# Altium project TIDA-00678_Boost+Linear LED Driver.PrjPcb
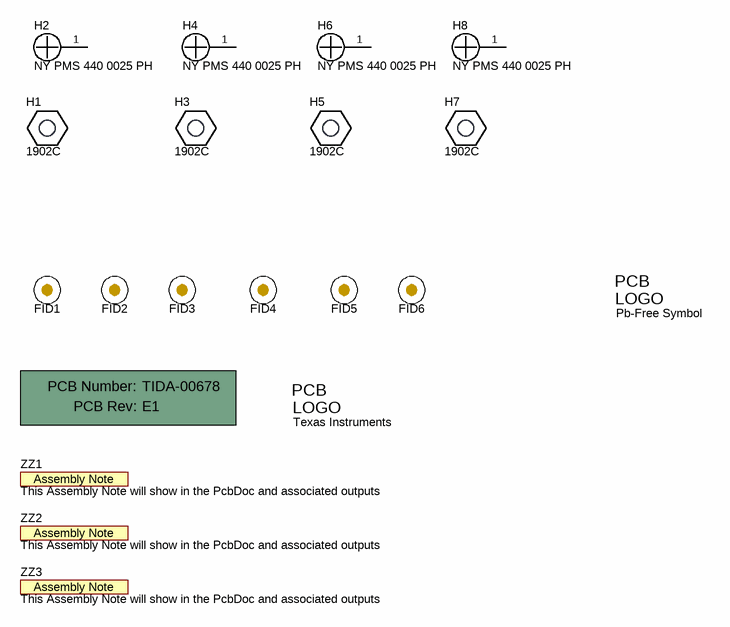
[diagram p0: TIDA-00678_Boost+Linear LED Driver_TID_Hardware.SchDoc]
CopyrightYear: 2015; EVM_Orderable: N/A; PCB_Layout: Robert Regensbureger; PCB_Rev: E1; PRJ_Customer: Public Release; PRJ_Engineer: Robert Regensburger; PRJ_Number: TIDA-00678; PRJ_Title: Boost+Linear LED Driver; SCH_Rev: E1; TechSupport: http://www.ti.com/support; TID: TIDA-00678
3 sheets, 184 parts. Net scope: global (net labels, ports and power ports of the same name join across sheets).
Board file: TIDA-00678_Boost+Linear LED Driver.PcbDoc
Sheets:
  TIDA-00678_Boost+Linear LED Driver_TID_Hardware.SchDoc
  TIDA-00678_Boost+Linear LED Driver 1.SchDoc
  TIDA-00678_Boost+Linear LED Driver 2.SchDoc

## Sheet TIDA-00678_Boost+Linear LED Driver_TID_Hardware.SchDoc: Boost+Linear LED Driver
size 431 x 279 mm; Date: Not shown in title block; ApprovedBy: Not shown in title block; CheckedBy: Not shown in title block; Author: Not shown in title block; CompanyName: Not shown in title block; Engineer: Not shown in title block; Organization: Not shown in title block; Address1: Not shown in title block; Address2: Not shown in title block; Address3: Not shown in title block; Address4: Not shown in title block; DocumentNumber: 4; Revision: Use project parameter SCH_Rev; SheetNumber: 4; SheetTotal: 4; PageSetup: Record=PageOptions¦CenterHorizontal=True¦CenterVertical=True¦PrintScale=1.00¦XCorrection=1.00¦YCorrection=1.00¦PrintKind=0¦BorderSize=5000000¦LeftOffset=0¦BottomOffset=0¦Orientation=2¦PaperLength=1000¦PaperWidth=1000¦Scale=100¦PaperSource=15¦PrintQuality=600¦MediaType=1¦DitherType=10¦PaperKind=Letter¦PrintScaleMode=1

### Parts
!PCB1  Printed Circuit Board  (value not drawn)  (mechanical)
FID1  Fiducial  [Fiducial10-20]  (value not drawn)
FID2  Fiducial  [Fiducial10-20]  (value not drawn)
FID3  Fiducial  [Fiducial10-20]  (value not drawn)
FID4  Fiducial  [Fiducial10-20]  (value not drawn)
FID5  Fiducial  [Fiducial10-20]  (value not drawn)
FID6  Fiducial  [Fiducial10-20]  (value not drawn)
H1  1902C  [Keystone_1902C]
H2  NY PMS 440 0025 PH  [NY PMS 440 0025 PH]
H3  1902C  [Keystone_1902C]
H4  NY PMS 440 0025 PH  [NY PMS 440 0025 PH]
H5  1902C  [Keystone_1902C]
H6  NY PMS 440 0025 PH  [NY PMS 440 0025 PH]
H7  1902C  [Keystone_1902C]
H8  NY PMS 440 0025 PH  [NY PMS 440 0025 PH]
Logo1  Texas Instruments  [TI_Symbol_Overlay_Medium]  (no BOM)
Logo2  Pb-Free Symbol  [Pb-Free_Overlay_Small]  (no BOM)
ZZ1  This Assembly Note will show in the PcbDoc and associated outputs  [AssemblyNote]  (no BOM)
ZZ2  This Assembly Note will show in the PcbDoc and associated outputs  [AssemblyNote]  (no BOM)
ZZ3  This Assembly Note will show in the PcbDoc and associated outputs  [AssemblyNote]  (no BOM)

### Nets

Not connected (* = marked no-connect by the designer): H2 1; H4 1; H6 1; H8 1

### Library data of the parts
!PCB1 = PCB: Manufacturer: Any; PartNumber: TIDA-00678; SymbolCreator: a0412235
FID1-FID6 = Fiducial: Fiducial mark.  There is nothing to buy or mount.; SymbolCreator: codlsc
H1 H3 H5 H7 = 1902C: Standoff, Hex, 0.5"L #4-40 Nylon; Manufacturer: Keystone; CompType: Hardware; SymbolCreator: a0412235
H2 H4 H6 H8 = NY PMS 440 0025 PH: Machine Screw, Round, #4-40 x 1/4, Nylon, Philips panhead; Manufacturer: B&F Fastener Supply; CompType: Hardware; SymbolCreator: codlsc; U/M: EA
Logo1 = TI_Logo: Texas Instrument Corporate Signature; SymbolCreator: a0412235
Logo2 = Pb-Free: SymbolCreator: a0412235
ZZ1-ZZ3 = AssemblyNote: SymbolCreator: codlsc

## Sheet TIDA-00678_Boost+Linear LED Driver 1.SchDoc: Boost+Linear LED Driver
size 431 x 279 mm; Date: Not shown in title block; ApprovedBy: Not shown in title block; CheckedBy: Not shown in title block; Author: Not shown in title block; CompanyName: Not shown in title block; DrawnBy: Robert Regensburger; Engineer: Not shown in title block; Organization: Not shown in title block; Address1: Not shown in title block; Address2: Not shown in title block; Address3: Not shown in title block; Address4: Not shown in title block; DocumentNumber: 2; Revision: Use project parameter SCH_Rev; SheetNumber: 2; SheetTotal: 4; PageSetup: Record=PageOptions¦CenterHorizontal=True¦CenterVertical=True¦PrintScale=0.62¦XCorrection=1.00¦YCorrection=1.00¦PrintKind=0¦BorderSize=5000000¦LeftOffset=0¦BottomOffset=0¦Orientation=2¦PaperLength=1000¦PaperWidth=1000¦Scale=100¦PaperSource=15¦PrintQuality=600¦MediaType=1¦DitherType=10¦PrintScaleMode=1¦PaperKind=Letter
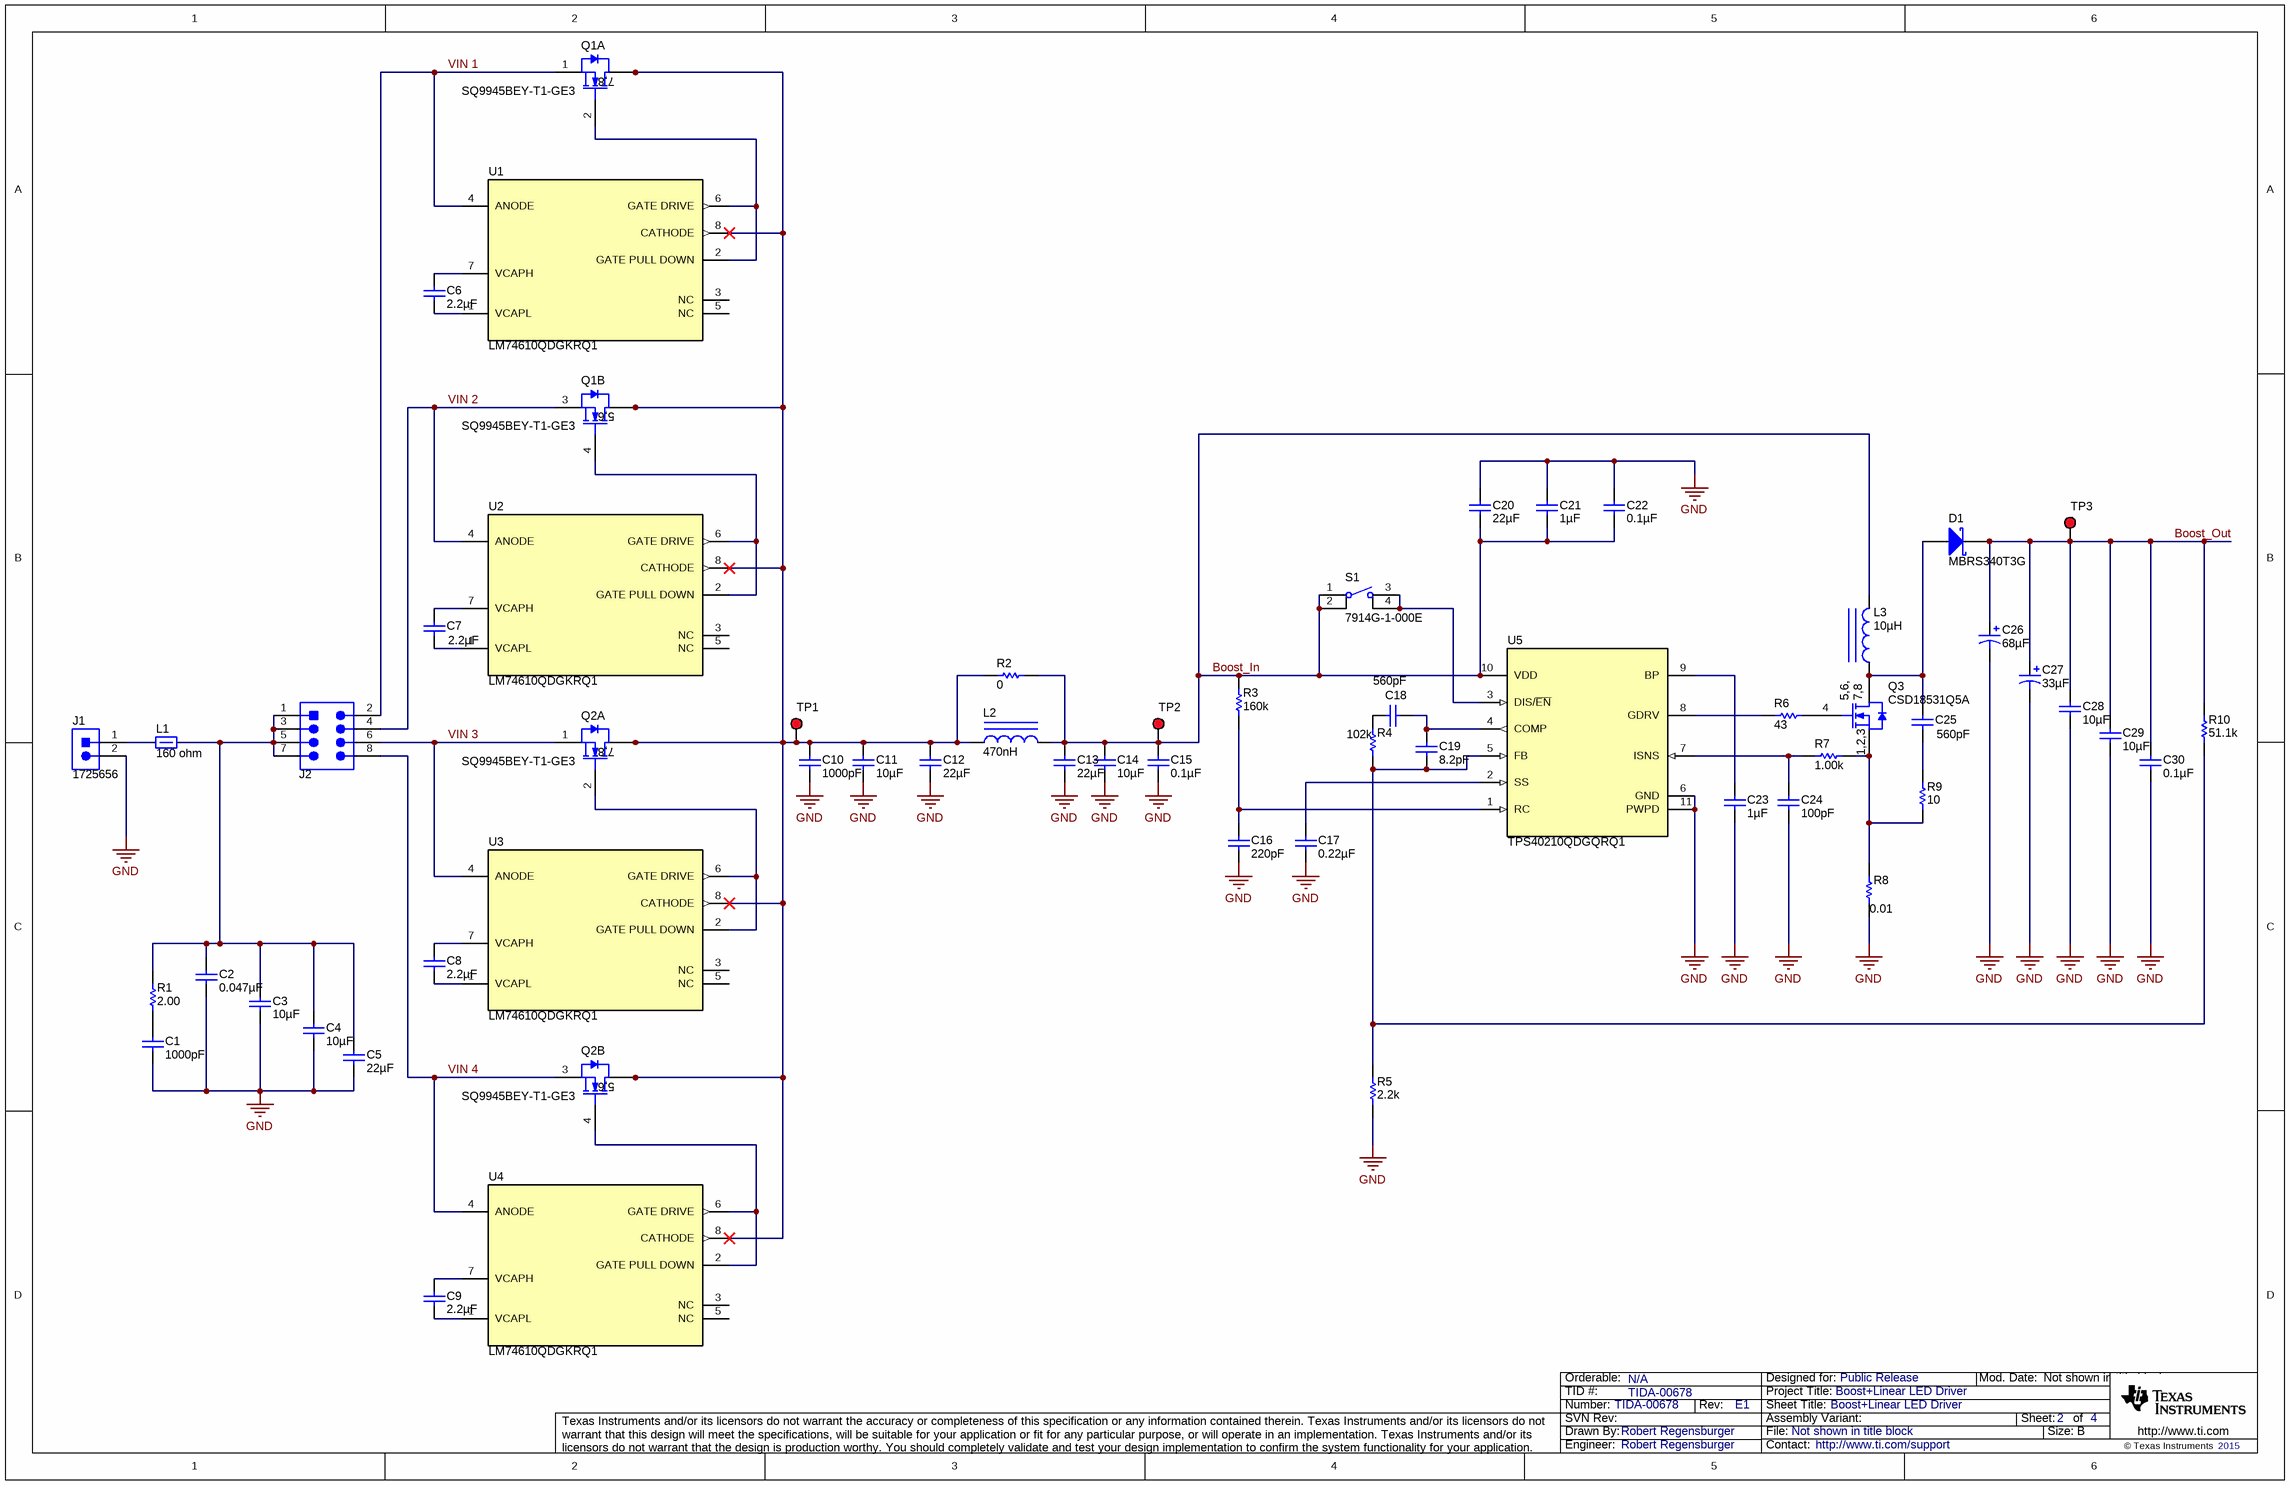
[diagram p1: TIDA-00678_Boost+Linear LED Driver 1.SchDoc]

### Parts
C1  ValueDisplayed: 1000pF  [0603]  (hidden comment: GRM188R72A102KA01D)
C2  ValueDisplayed: 0.047µF  [0603]  (hidden comment: GRM188R71H473KA61D)
C3  ValueDisplayed: 10µF  [1210_270]  (hidden comment: GRM32ER71H106KA12L)
C4  ValueDisplayed: 10µF  [1210_270]  (hidden comment: GRM32ER71H106KA12L)
C5  ValueDisplayed: 22µF  [0805_HV]  (hidden comment: C2012JB1V226M125AC)
C6  ValueDisplayed: 2.2µF  [0805_HV]  (hidden comment: C2012X5R1H225K125AB)
C7  ValueDisplayed: 2.2µF  [0805_HV]  (hidden comment: C2012X5R1H225K125AB)
C8  ValueDisplayed: 2.2µF  [0805_HV]  (hidden comment: C2012X5R1H225K125AB)
C9  ValueDisplayed: 2.2µF  [0805_HV]  (hidden comment: C2012X5R1H225K125AB)
C10  ValueDisplayed: 1000pF  [0603]  (hidden comment: GRM188R72A102KA01D)
C11  ValueDisplayed: 10µF  [1210_270]  (hidden comment: GRM32ER71H106KA12L)
C12  ValueDisplayed: 22µF  [0805_HV]  (hidden comment: C2012JB1V226M125AC)
C13  ValueDisplayed: 22µF  [0805_HV]  (hidden comment: C2012JB1V226M125AC)
C14  ValueDisplayed: 10µF  [1210_270]  (hidden comment: GRM32ER71H106KA12L)
C15  ValueDisplayed: 0.1µF  [0603]  (hidden comment: C1608X7R1H104K080AA)
C16  ValueDisplayed: 220pF  [0603]  (hidden comment: 06035A221FAT2A)
C17  ValueDisplayed: 0.22µF  [0603]  (hidden comment: C0603C224K4RACTU)
C18  ValueDisplayed: 560pF  [0603]  (hidden comment: 06035A561JAT2A)
C19  ValueDisplayed: 8.2pF  [0603]  (hidden comment: 06035A8R2CAT2A)
C20  ValueDisplayed: 22µF  [0805_HV]  (hidden comment: C2012JB1V226M125AC)
C21  ValueDisplayed: 1µF  [0603]  (hidden comment: UMK107AB7105KA-T)
C22  ValueDisplayed: 0.1µF  [0603]  (hidden comment: C1608X7R1H104K080AA)
C23  ValueDisplayed: 1µF  [0603]  (hidden comment: GRM185C81A105KE36D)
C24  ValueDisplayed: 100pF  [0603]  (hidden comment: 06035A101FAT2A)
C25  ValueDisplayed: 560pF  [0603]  (hidden comment: 06035A561JAT2A)
C26  ValueDisplayed: 68µF  [SM_RADIAL_6.3BMM]  (hidden comment: UUD1V680MCL1GS)
C27  ValueDisplayed: 33µF  [SM_RADIAL_6.3BMM]  (hidden comment: EEHZA1H330XP)
C28  ValueDisplayed: 10µF  [1210_270]  (hidden comment: GRM32ER71H106KA12L)
C29  ValueDisplayed: 10µF  [1210_270]  (hidden comment: GRM32ER71H106KA12L)
C30  ValueDisplayed: 0.1µF  [0603]  (hidden comment: C1608X7R1H104K080AA)
D1  MBRS340T3G  [SMC]
J1  1725656  [CONN_1725656]
J2  PEC04DAAN  [CONN_PEC04DAAN]  (value not drawn)
L1  value 160 ohm  [1206M]  (hidden comment: HI1206T161R-10)
L2  ValueDisplayed: 470nH  [WE-LHMI_4020]  (hidden comment: 744373240047)
L3  ValueDisplayed: 10µH  [SRP1250]  (hidden comment: SRP1250-100M)
Q1  SQ9945BEY-T1-GE3  [SOIC-8]  (parts A,B of 2)
Q2  SQ9945BEY-T1-GE3  [SOIC-8]  (parts A,B of 2)
Q3  CSD18531Q5A  [TRANS_NexFET_Q5A]
R1  ValueDisplayed: 2.00  [0603]  (hidden comment: CRCW06032R00FKEA)
R2  ValueDisplayed: 0  [0603]  (hidden comment: CRCW06030000Z0EA)
R3  ValueDisplayed: 160k  [0603]  (hidden comment: CRCW0603160KFKEA)
R4  ValueDisplayed: 102k  [0603]  (hidden comment: CRCW0603102KFKEA)
R5  ValueDisplayed: 2.2k  [0603]  (hidden comment: CRCW06032K20JNEA)
R6  ValueDisplayed: 43  [0603]  (hidden comment: CRCW060343R0JNEA)
R7  ValueDisplayed: 1.00k  [0603]  (hidden comment: CRCW06031K00FKEA)
R8  ValueDisplayed: 0.01  [3015]  (hidden comment: KRL7638-C-R010-F-T1)
R9  ValueDisplayed: 10  [0603]  (hidden comment: CRCW060310R0JNEA)
R10  ValueDisplayed: 51.1k  [0603]  (hidden comment: RC0603FR-0751K1L)
S1  7914G-1-000E  [SW_7914G-1-000E]
TP1  5000  [Keystone5000]  (value not drawn)
TP2  5000  [Keystone5000]  (value not drawn)
TP3  5000  [Keystone5000]  (value not drawn)
U1  LM74610QDGKRQ1  [DGK0008A_N]
U2  LM74610QDGKRQ1  [DGK0008A_N]
U3  LM74610QDGKRQ1  [DGK0008A_N]
U4  LM74610QDGKRQ1  [DGK0008A_N]
U5  TPS40210QDGQRQ1  [DGQ0010D_N]

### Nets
GND: C1.2 C2.2 C3.2 C4.2 C5.2 C10.2 C11.2 C12.2 C13.2 C14.2 C15.2 C16.2 C17.2 C20.1 C21.1 C22.1 C23.2 C24.2 C26.2(-) C27.2(-) C28.2 C29.2 C30.2 J1.2 R5.1 R8.1 U5.6(GND) U5.11(PWPD)  [project net REVGND]
Boost_In: C13.1 C14.1 C15.1 C20.2 C21.2 C22.2 L2.2 L3.2 R2.1 R3.2 S1.1 S1.2 TP2.1 U5.10(VDD)
Boost_Out: C26.1(+) C27.1(+) C28.1 C29.1 C30.1 D1.1(K) R10.2 TP3.1
VIN 1: J2.2 Q1.1(S) U1.4(ANODE)
VIN 2: J2.4 Q1.3(S) U2.4(ANODE)
VIN 3: J2.6 Q2.1(S) U3.4(ANODE)
VIN 4: J2.8 Q2.3(S) U4.4(ANODE)
NetC1_1: C1.1 R1.1
NetC2_1: C2.1 C3.1 C4.1 C5.1 J2.1 J2.3 J2.5 J2.7 L1.2 R1.2
NetC6_1: C6.1 U1.7(VCAPH)
NetC6_2: C6.2 U1.1(VCAPL)
NetC7_1: C7.1 U2.7(VCAPH)
NetC7_2: C7.2 U2.1(VCAPL)
NetC8_1: C8.1 U3.7(VCAPH)
NetC8_2: C8.2 U3.1(VCAPL)
NetC9_1: C9.1 U4.7(VCAPH)
NetC9_2: C9.2 U4.1(VCAPL)
NetC10_1: C10.1 C11.1 C12.1 L2.1 Q1.5(D) Q1.6(D) Q1.7(D) Q1.8(D) Q2.5(D) Q2.6(D) Q2.7(D) Q2.8(D) R2.2 TP1.1 U1.8(CATHODE) U2.8(CATHODE) U3.8(CATHODE) U4.8(CATHODE)
NetC16_1: C16.1 R3.1 U5.1(RC)
NetC17_1: C17.1 U5.2(SS)
NetC18_1: C18.1 C19.1 U5.4(COMP)
NetC18_2: C18.2 R4.2
NetC19_2: C19.2 R4.1 R5.2 R10.1 U5.5(FB)
NetC23_1: C23.1 U5.9(BP)
NetC24_1: C24.1 R7.1 U5.7(ISNS)
NetC25_1: C25.1 D1.2(A) L3.1 Q3.5(D) Q3.6(D) Q3.7(D) Q3.8(D) Q3.9(D)
NetC25_2: C25.2 R9.2
NetJ1_1: J1.1 L1.1
NetQ1_2: Q1.2(G) U1.2(GATE_PULL_DOWN) U1.6(GATE_DRIVE)
NetQ1_4: Q1.4(G) U2.2(GATE_PULL_DOWN) U2.6(GATE_DRIVE)
NetQ2_2: Q2.2(G) U3.2(GATE_PULL_DOWN) U3.6(GATE_DRIVE)
NetQ2_4: Q2.4(G) U4.2(GATE_PULL_DOWN) U4.6(GATE_DRIVE)
NetQ3_1: Q3.1(S) Q3.2(S) Q3.3(S) R7.2 R8.2 R9.1
NetQ3_4: Q3.4(G) R6.2
NetR6_1: R6.1 U5.8(GDRV)
NetS1_3: S1.3 S1.4 U5.3(DIS/~{EN})

Not connected (* = marked no-connect by the designer): U1 3(NC) 5(NC); U2 3(NC) 5(NC); U3 3(NC) 5(NC); U4 3(NC) 5(NC)

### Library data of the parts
C1 C10 = GRM188R72A102KA01D: CAP, CERM, 1000 pF, 100 V, +/- 10%, X7R, 0603; Manufacturer: MuRata; Polarized: N; CompType: Capacitor; Value: 1000pF; U/M: EA; Cap_F: 0.000000001; Tolerance_%: 10; Value1: Unknown; VDC_V: 100; Value2: 100V; TaMin_C: -55; TaMax_C: 125; AEC Category: Q200
C2 = GRM188R71H473KA61D: CAP, CERM, 0.047 µF, 50 V, +/- 10%, X7R, 0603; Manufacturer: MuRata; Polarized: N; CompType: Capacitor; Value: 0.047uF; U/M: EA; Cap_F: 0.000000047; Tolerance_%: 10; Value1: Unknown; VDC_V: 50; Value2: 50V; TaMin_C: -55; TaMax_C: 125; AEC Category: Q200
C3 C4 C11 C14 C28 C29 = GRM32ER71H106KA12L: CAP, CERM, 10 µF, 50 V, +/- 10%, X7R, 1210; Manufacturer: MuRata; Polarized: N; CompType: Capacitor; Value: 10uF; U/M: EA; Cap_F: 0.00001; Tolerance_%: 10; Value1: Unknown; VDC_V: 50; Value2: 50V; TaMin_C: -55; TaMax_C: 125; Cap_Case: 1210; AEC Category: Q200
C5 C12 C13 C20 = C2012JB1V226M125AC: CAP, CERM, 22 µF, 35 V, +/- 20%, JB, 0805; Manufacturer: TDK; Polarized: N; CompType: Capacitor; Value: 22uF; U/M: EA; Cap_F: 0.000022; Tolerance_%: 20; Value1: Unknown; VDC_V: 35; Value2: 35V; TaMin_C: -25; TaMax_C: 85; Cap_Case: 0805; AEC Category: Q200
C6-C9 = C2012X5R1H225K125AB: CAP, CERM, 2.2 µF, 50 V, +/- 10%, X5R, 0805; Manufacturer: TDK; Polarized: N; CompType: Capacitor; Value: 2.2uF; U/M: EA; Cap_F: 0.0000022; Tolerance_%: 10; Value1: Unknown; VDC_V: 50; Value2: 50V; TaMin_C: -55; TaMax_C: 85; Cap_Case: 0805; AEC Category: Q200
C15 C22 C30 = C1608X7R1H104K080AA: CAP, CERM, 0.1 µF, 50 V, +/- 10%, X7R, 0603; Manufacturer: TDK; Polarized: N; CompType: Capacitor; Value: 0.1uF; U/M: EA; Cap_F: 0.0000001; Tolerance_%: 10; Value1: Unknown; VDC_V: 50; Value2: 50V; TaMin_C: -55; TaMax_C: 125; AEC Category: Q200
C16 = 06035A221FAT2A: CAP, CERM, 220 pF, 50 V, +/- 1%, C0G/NP0, 0603; Manufacturer: AVX; Polarized: N; CompType: Capacitor; Value: 220pF; U/M: EA; Cap_F: 0.00000000022; Tolerance_%: 1; ESR_ohm: 0.083; Value1: 0.083 ohm; VDC_V: 50; Value2: 50V; TaMin_C: -55; TaMax_C: 125; AEC Category: Q200
C17 = C0603C224K4RACTU: CAP, CERM, 0.22 µF, 16 V, +/- 10%, X7R, 0603; Manufacturer: Kemet; Polarized: N; CompType: Capacitor; Value: 0.22uF; U/M: EA; Cap_F: 0.00000022; Tolerance_%: 10; Value1: Unknown; VDC_V: 16; Value2: 16V; TaMin_C: -55; TaMax_C: 125; AEC Category: Q200
C18 C25 = 06035A561JAT2A: CAP, CERM, 560 pF, 50 V, +/- 5%, C0G/NP0, 0603; Manufacturer: AVX; Polarized: N; CompType: Capacitor; Value: 560pF; U/M: EA; Cap_F: 0.00000000056; Tolerance_%: 5; ESR_ohm: 0.059; Value1: 0.059 ohm; VDC_V: 50; Value2: 50V; TaMin_C: -55; TaMax_C: 125; AEC Category: Q200
C19 = 06035A8R2CAT2A: CAP, CERM, 8.2 pF, 50 V, +/- 3%, C0G/NP0, 0603; Manufacturer: AVX; Polarized: N; CompType: Capacitor; Value: 8.2pF; U/M: EA; Cap_F: 0.0000000000082; Tolerance_%: 3; ESR_ohm: 0.452; Value1: 0.452 ohm; VDC_V: 50; Value2: 50V; TaMin_C: -55; TaMax_C: 125; AEC Category: Q200
C21 = UMK107AB7105KA-T: CAP, CERM, 1 µF, 50 V, +/- 10%, X7R, 0603; Manufacturer: Taiyo Yuden; Polarized: N; CompType: Capacitor; Value: 1uF; U/M: EA; Cap_F: 0.000001; Tolerance_%: 10; Value1: Unknown; VDC_V: 50; Value2: 50V; TaMin_C: -55; TaMax_C: 125; AEC Category: Q200
C23 = GRM185C81A105KE36D: CAP, CERM, 1 µF, 10 V, +/- 10%, X6S, 0603; Manufacturer: MuRata; Polarized: N; CompType: Capacitor; Value: 1uF; U/M: EA; Cap_F: 0.000001; Tolerance_%: 10; Value1: Unknown; Value2: 10V; TaMin_C: -55; TaMax_C: 105; AEC Category: Q200
C24 = 06035A101FAT2A: CAP, CERM, 100 pF, 50 V, +/- 1%, C0G/NP0, 0603; Manufacturer: AVX; Polarized: N; CompType: Capacitor; Value: 100pF; U/M: EA; Cap_F: 0.0000000001; Tolerance_%: 1; Value1: Unknown; VDC_V: 50; Value2: 50V; TaMin_C: -55; TaMax_C: 125; AEC Category: Q200
C26 = UUD1V680MCL1GS: CAP, AL, 68 µF, 35 V, +/- 20%, 0.34 ohm, SMD; Manufacturer: Nichicon; Polarized: Y; CompType: Capacitor; Value: 68uF; U/M: EA; Cap_F: 0.000068; Tolerance_%: 20; VDC_V: 35; Value2: 35V; ESR_ohm: 0.34; IRMS_A: 0.28; TaMin_C: -55; TaMax_C: 105; Cap_Case: 6.3x7.7; AEC Category: Q200
C27 = EEHZA1H330XP: CAP, Polymer Hybrid, 33 µF, 50 V, +/- 20%, 40 ohm, 6.3x7.7 SMD; Manufacturer: Panasonic; Polarized: Y; CompType: Capacitor; Value: 33uF; U/M: EA; Cap_F: 0.000033; Tolerance_%: 20; Value1: 40 ohm; VDC_V: 50; Value2: 50V; ESR_ohm: 40; IRMS_A: 1.6; TaMin_C: -55; TaMax_C: 105; AEC Category: Q200
D1 = MBRS340T3G: Diode, Schottky, 40 V, 3 A, SMC; Manufacturer: ON Semiconductor; U/M: EA; Vf_V: 0.525; Value: 40V; Value1: 3A; Value2: 0.525V; Io_A: 3; Vr_V: 40; TJmax_C: 125; RJC_CperW: 11; AEC Category: Q101
J1 = 1725656: Terminal Block, 100mil, 2x1, 6A, 63V, TH; Manufacturer: Phoenix Contact; SymbolCreator: a0412235
J2 = PEC04DAAN: Header, 100mil, 4x2, Tin, TH; Manufacturer: Sullins Connector Solutions; SymbolCreator: a0411947; Pitch_mm: 2.54; Gender: Male; Shrouded: N; Row_Count: 2; Current_A: 3; Voltage_V: 1800; Cert_UL: Y
L1 = HI1206T161R-10: Ferrite Bead, 160 ohm @ 100 MHz, 6 A, 1206; Manufacturer: Laird-Signal Integrity Products; Imax_A: 6; DCR_ohm: 0.018; Value1: 0.018 ohm; Value2: 6A; ZTyp@100MHz_Ohm: 160; Ztyp@1GHz_Ohm: 127
L2 = 744373240047: Inductor, Shielded Drum Core, Powdered Iron, 470 nH, 6.8 A, 0.0112 ohm, SMD; Manufacturer: Wurth Elektronik; Value: 470nH; Ind_H: 470.0E-9; Imax_A: 6.8; Irms: 6.8A @ 40C rise; Isat: 14.5A @ 20% inductance drop; DCR_ohm: 0.0112; Value2: 6.8A; AEC Category: Q200
L3 = SRP1250-100M: Inductor, Powdered Iron, 10 µH, 10 A, 0.0255 ohm, SMD; Manufacturer: Bourns; Value: 10uH; Ind_H: 10.0E-6; Imax_A: 10; Irms: 10A @ 40C rise; Isat: 16A @ 20% inductance drop; DCR_ohm: 0.0255; Value2: 10A; AEC Category: Q200
Q1 Q2 = SQ9945BEY-T1-GE3: MOSFET, N-CH, 60 V, 5.4 A, SOIC-8; Manufacturer: Vishay-Siliconix; Alternate Manufacturer: None; U/M: EA; ChType: N; Value: 60V; VdsMax_V: 60; Value1: 0.082 ohm; Rdson45_ohm: 0.082; Value2: 8 nC; QgTyp_nC: 8; Vgs_V: 20; IdsMax_A: 5.4; AEC Category: Q101
Q3 = CSD18531Q5A: MOSFET, N-CH, 60 V, 19 A, SON 5x6mm; Manufacturer: Texas Instruments; Alternate Manufacturer: None; U/M: EA; ChType: N; Value: 60V; VdsMax_V: 60; Value1: 0.0044 ohm; Rdson45_ohm: 0.0044; Value2: 18 nC; QgTyp_nC: 18; Vgs_V: 20; IdsMax_A: 19; AEC Category: Q101
R1 = CRCW06032R00FKEA: RES, 2.00, 1%, 0.1 W, 0603; Manufacturer: Vishay-Dale; CompType: Resistor; Value: 2.00; Res_ohm: 2; Value_Code: 2R00; Tolerance_%: 1; Power_W: 0.1; Value2: 0.1W; VDC_V: 75; TempCo: 100 ppm/C; EIA_Code: E96; U/M: EA; AEC Category: Q200
R2 = CRCW06030000Z0EA: RES, 0, 5%, 0.1 W, 0603; Manufacturer: Vishay-Dale; CompType: Resistor; Value: 0; Value_Code: 0000; Tolerance_%: 5; Power_W: 0.1; Value2: 0.1W; VDC_V: 75; TempCo: 200 ppm/C; EIA_Code: E24; U/M: EA; AEC Category: Q200
R3 = CRCW0603160KFKEA: RES, 160 k, 1%, 0.1 W, 0603; Manufacturer: Vishay-Dale; CompType: Resistor; Value: 160k; Res_ohm: 160000; Tolerance_%: 1; Power_W: 0.1; Value2: 0.1W; VDC_V: 75; TempCo: 100 ppm/C; U/M: EA; AEC Category: Q200
R4 = CRCW0603102KFKEA: RES, 102 k, 1%, 0.1 W, 0603; Manufacturer: Vishay-Dale; CompType: Resistor; Value: 102k; Res_ohm: 102000; Tolerance_%: 1; Power_W: 0.1; Value2: 0.1W; VDC_V: 75; TempCo: 100 ppm/C; EIA_Code: E96; U/M: EA; AEC Category: Q200
R5 = CRCW06032K20JNEA: RES, 2.2 k, 5%, 0.1 W, 0603; Manufacturer: Vishay-Dale; CompType: Resistor; Value: 2.2k; Res_ohm: 2200; Value_Code: 2k20; Tolerance_%: 5; Power_W: 0.1; Value2: 0.1W; VDC_V: 75; TempCo: 200 ppm/C; EIA_Code: E24; U/M: EA; AEC Category: Q200
R6 = CRCW060343R0JNEA: RES, 43, 5%, 0.1 W, 0603; Manufacturer: Vishay-Dale; CompType: Resistor; Value: 43; Value_Code: 43R0; Tolerance_%: 5; Power_W: 0.1; Value2: 0.1W; VDC_V: 75; TempCo: 200 ppm/C; EIA_Code: E24; U/M: EA; AEC Category: Q200
R7 = CRCW06031K00FKEA: RES, 1.00 k, 1%, 0.1 W, 0603; Manufacturer: Vishay-Dale; CompType: Resistor; Value: 1.00k; Res_ohm: 1000; Value_Code: 1k00; Tolerance_%: 1; Power_W: 0.1; Value2: 0.1W; VDC_V: 75; TempCo: 100 ppm/C; EIA_Code: E96; U/M: EA; AEC Category: Q200
R8 = KRL7638-C-R010-F-T1: RES, 0.01, 1%, 4 W, 3015 WIDE; Manufacturer: Susumu Co Ltd; CompType: Resistor; Value: 0.01; Value_Code: R010; Tolerance_%: 1; Power_W: 4; Value2: 4W; TempCo: 50 ppm/C; EIA_Code: E96; U/M: EA; AEC Category: Q200
R9 = CRCW060310R0JNEA: RES, 10, 5%, 0.1 W, 0603; Manufacturer: Vishay-Dale; CompType: Resistor; Value: 10; Value_Code: 10R0; Tolerance_%: 5; Power_W: 0.1; Value2: 0.1W; VDC_V: 75; TempCo: 200 ppm/C; EIA_Code: E24; U/M: EA; AEC Category: Q200
R10 = RC0603FR-0751K1L: RES, 51.1 k, 1%, 0.1 W, 0603; Manufacturer: Yageo America; CompType: Resistor; Value: 51.1k; Res_ohm: 51100; Value_Code: 51k1; Tolerance_%: 1; Power_W: 0.1; Value2: 0.1W; VDC_V: 150; TempCo: 200 ppm/C; EIA_Code: E96; U/M: EA; AEC Category: Q200
S1 = 7914G-1-000E: Switch, Tactile, SPST-NO, 0.1A, 16V, SMT; Manufacturer: Bourns; SymbolCreator: a0412235; VDC_V: 16; SwitchFunction: Off-Mom; PositionCount: 1; CurrentRating_mA: 100
TP1-TP3 = 5000: Test Point, Miniature, Red, TH; Manufacturer: Keystone; CompType: Test Point Loop; ContactFinish: Silver
U1-U4 = LM74610QDGKRQ1: Smart Diode Controller, DGK0008A; Manufacturer: Texas Instruments; SymbolCreator: Altium; CompType: IC; U/M: EA
U5 = TPS40210QDGQRQ1: 4.5-V TO 52-V INPUT CURRENT MODE BOOST CONTROLLER, DGQ0010D; Manufacturer: Texas Instruments; SymbolCreator: a0412235; CompType: IC; U/M: EA

## Sheet TIDA-00678_Boost+Linear LED Driver 2.SchDoc: Boost+Linear LED Driver
size 431 x 279 mm; Date: Not shown in title block; ApprovedBy: Not shown in title block; CheckedBy: Not shown in title block; Author: Not shown in title block; CompanyName: Not shown in title block; DrawnBy: Robert Regensburger; Engineer: Not shown in title block; Organization: Not shown in title block; Address1: Not shown in title block; Address2: Not shown in title block; Address3: Not shown in title block; Address4: Not shown in title block; DocumentNumber: 3; Revision: Use project parameter SCH_Rev; SheetNumber: 3; SheetTotal: 4; PageSetup: Record=PageOptions¦CenterHorizontal=True¦CenterVertical=True¦PrintScale=0.66¦XCorrection=1.00¦YCorrection=1.00¦PrintKind=0¦BorderSize=5000000¦LeftOffset=0¦BottomOffset=0¦Orientation=2¦PaperLength=2970¦PaperWidth=2100¦Scale=100¦PaperSource=7¦PrintQuality=600¦MediaType=1¦DitherType=10¦PrintScaleMode=1¦PaperKind=A4¦PaperIndex=9
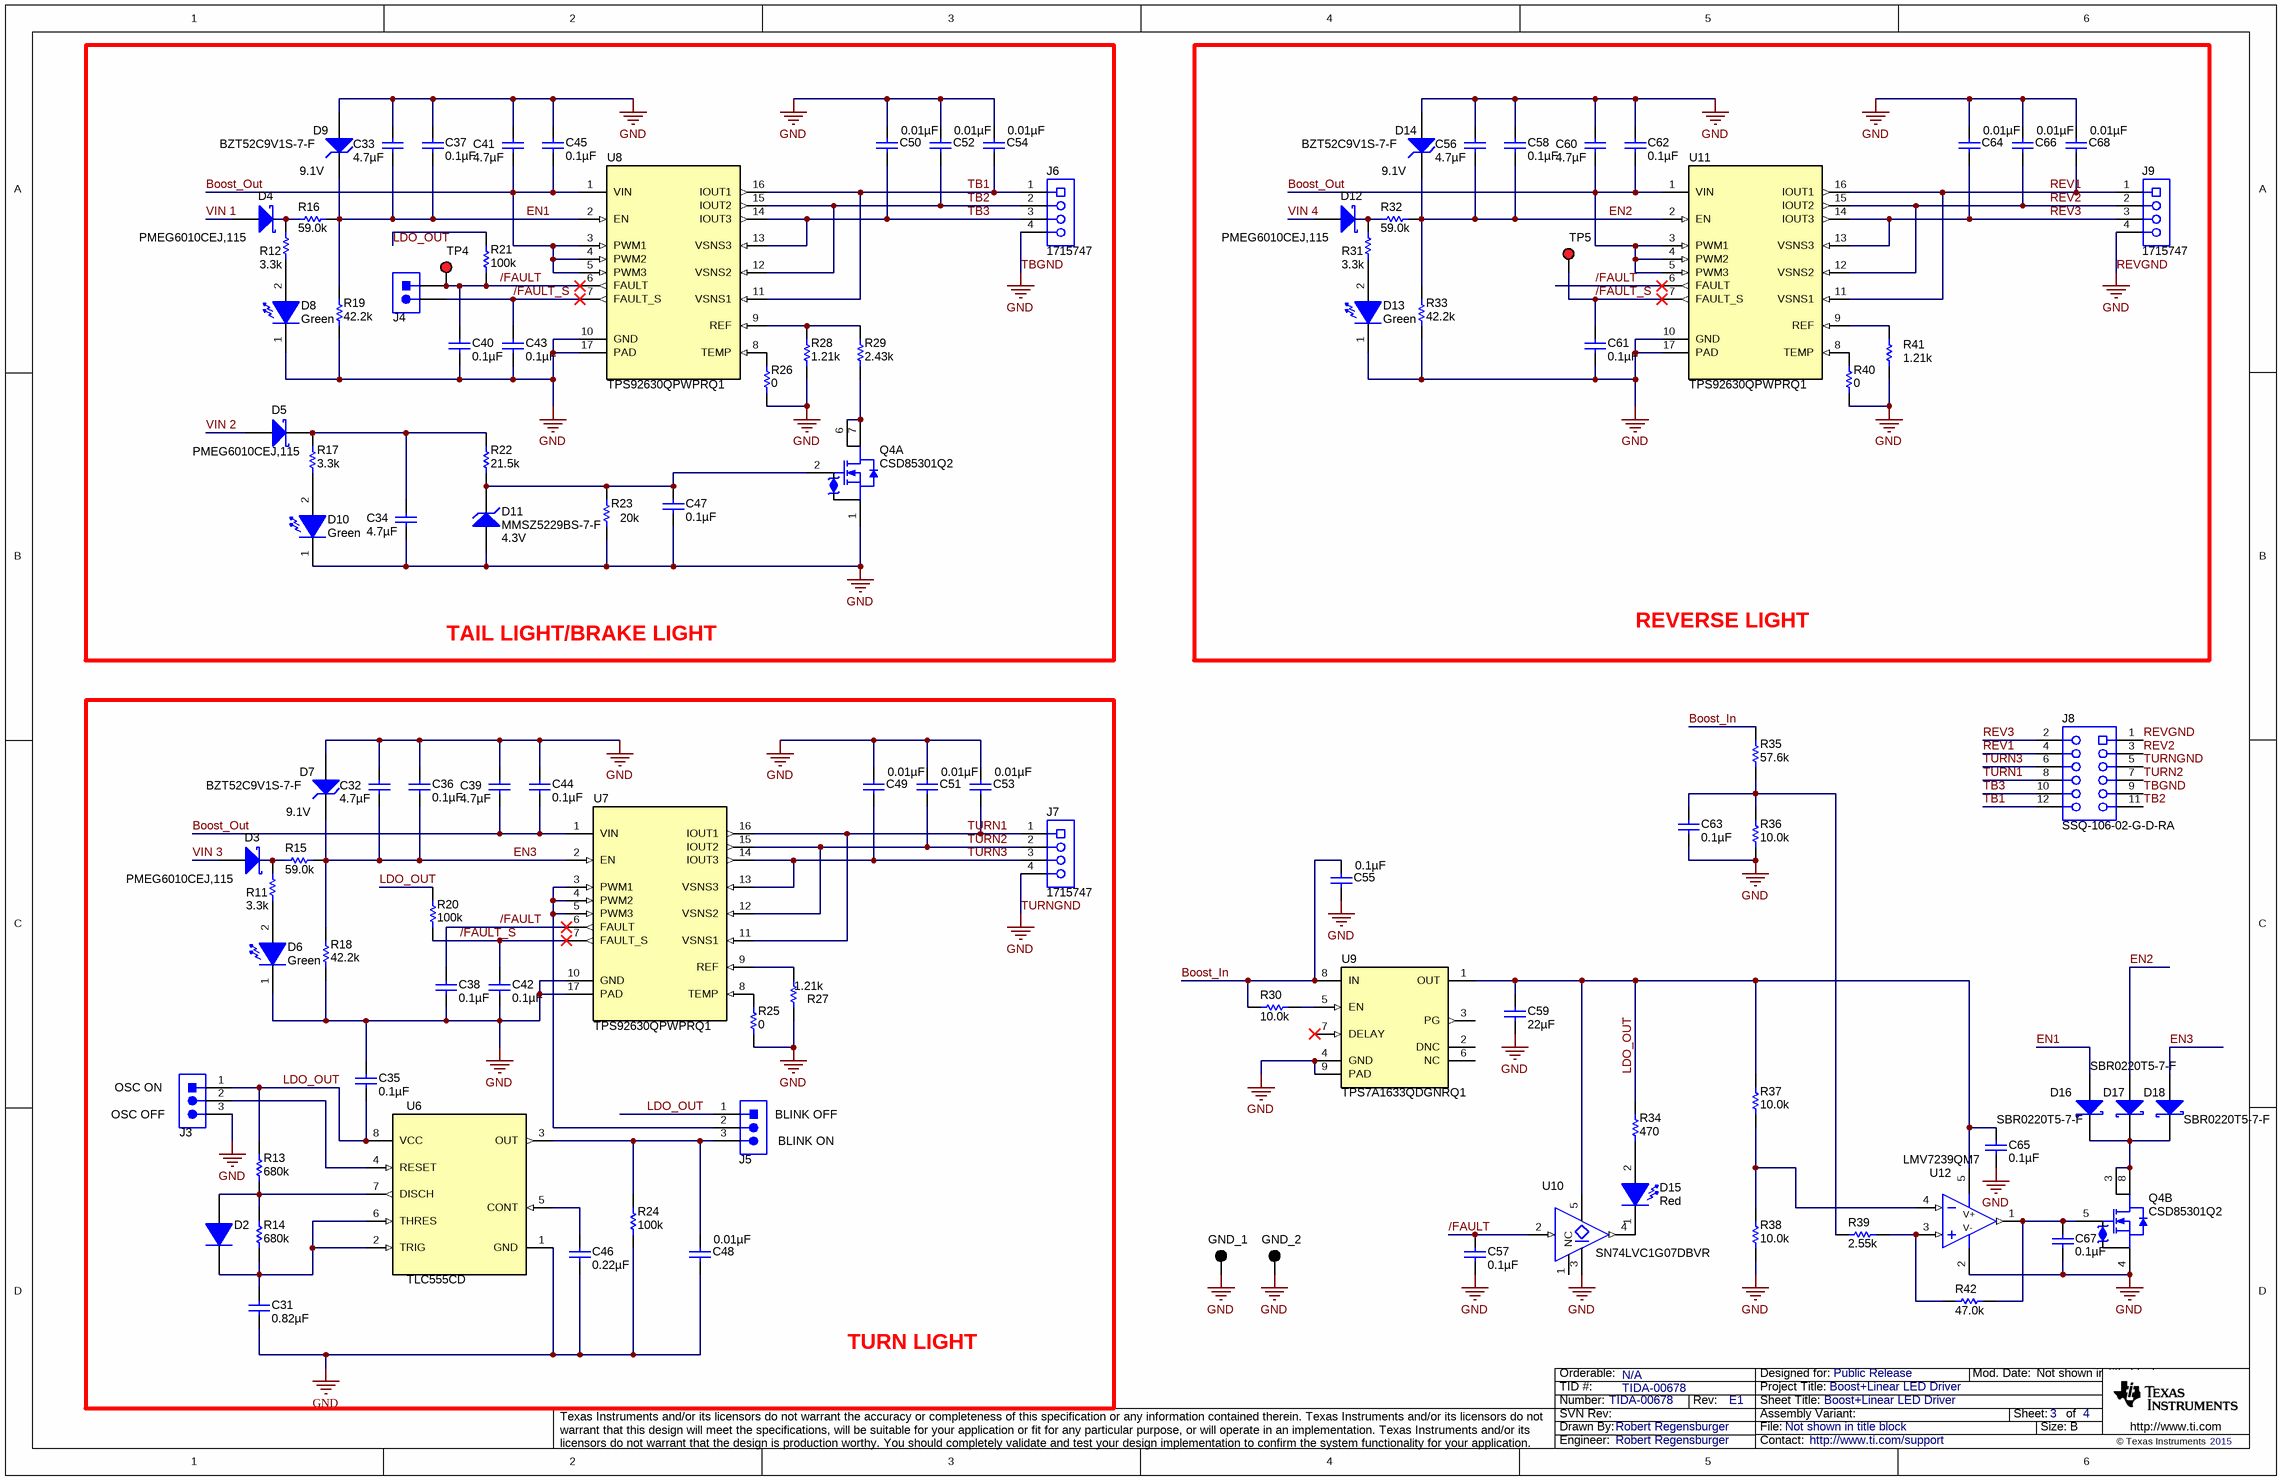
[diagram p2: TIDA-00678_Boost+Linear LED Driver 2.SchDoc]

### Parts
C31  ValueDisplayed: 0.82µF  [0805_HV]  (hidden comment: GRM219R71E824KA88D)
C32  ValueDisplayed: 4.7µF  [1206]  (hidden comment: GRM31CR71H475KA12L)
C33  ValueDisplayed: 4.7µF  [1206]  (hidden comment: GRM31CR71H475KA12L)
C34  ValueDisplayed: 4.7µF  [1206]  (hidden comment: GRM31CR71H475KA12L)
C35  ValueDisplayed: 0.1µF  [0603]  (hidden comment: 06035C104KAT2A)
C36  ValueDisplayed: 0.1µF  [0603]  (hidden comment: 06035C104KAT2A)
C37  ValueDisplayed: 0.1µF  [0603]  (hidden comment: 06035C104KAT2A)
C38  ValueDisplayed: 0.1µF  [0603]  (hidden comment: 06035C104KAT2A)
C39  ValueDisplayed: 4.7µF  [1206]  (hidden comment: GRM31CR71H475KA12L)
C40  ValueDisplayed: 0.1µF  [0603]  (hidden comment: 06035C104KAT2A)
C41  ValueDisplayed: 4.7µF  [1206]  (hidden comment: GRM31CR71H475KA12L)
C42  ValueDisplayed: 0.1µF  [0603]  (hidden comment: 06035C104KAT2A)
C43  ValueDisplayed: 0.1µF  [0603]  (hidden comment: 06035C104KAT2A)
C44  ValueDisplayed: 0.1µF  [0603]  (hidden comment: 06035C104KAT2A)
C45  ValueDisplayed: 0.1µF  [0603]  (hidden comment: 06035C104KAT2A)
C46  ValueDisplayed: 0.22µF  [0805_HV]  (hidden comment: 0805YC224JAT2A)
C47  ValueDisplayed: 0.1µF  [0603]  (hidden comment: 06035C104KAT2A)
C48  ValueDisplayed: 0.01µF  [0603]  (hidden comment: 06031C103JAT2A)
C49  ValueDisplayed: 0.01µF  [0603]  (hidden comment: 06031C103JAT2A)
C50  ValueDisplayed: 0.01µF  [0603]  (hidden comment: 06031C103JAT2A)
C51  ValueDisplayed: 0.01µF  [0603]  (hidden comment: 06031C103JAT2A)
C52  ValueDisplayed: 0.01µF  [0603]  (hidden comment: 06031C103JAT2A)
C53  ValueDisplayed: 0.01µF  [0603]  (hidden comment: 06031C103JAT2A)
C54  ValueDisplayed: 0.01µF  [0603]  (hidden comment: 06031C103JAT2A)
C55  ValueDisplayed: 0.1µF  [0603]  (hidden comment: C1608X7R1H104K)
C56  ValueDisplayed: 4.7µF  [1206]  (hidden comment: GRM31CR71H475KA12L)
C57  ValueDisplayed: 0.1µF  [0603]  (hidden comment: 0603YC104JAT2A)
C58  ValueDisplayed: 0.1µF  [0603]  (hidden comment: 06035C104KAT2A)
C59  ValueDisplayed: 22µF  [0603]  (hidden comment: C1608X5R1A226M080AC)
C60  ValueDisplayed: 4.7µF  [1206]  (hidden comment: GRM31CR71H475KA12L)
C61  ValueDisplayed: 0.1µF  [0603]  (hidden comment: 06035C104KAT2A)
C62  ValueDisplayed: 0.1µF  [0603]  (hidden comment: 06035C104KAT2A)
C63  ValueDisplayed: 0.1µF  [0603]  (hidden comment: 06035C104KAT2A)
C64  ValueDisplayed: 0.01µF  [0603]  (hidden comment: 06031C103JAT2A)
C65  ValueDisplayed: 0.1µF  [0603]  (hidden comment: 0603YC104JAT2A)
C66  ValueDisplayed: 0.01µF  [0603]  (hidden comment: 06031C103JAT2A)
C67  ValueDisplayed: 0.1µF  [0603]  (hidden comment: 0603YC104JAT2A)
C68  ValueDisplayed: 0.01µF  [0603]  (hidden comment: 06031C103JAT2A)
D2  1N4148W-7-F  [SOD-123]  (value not drawn)
D3  PMEG6010CEJ,115  [SOD-323F]
D4  PMEG6010CEJ,115  [SOD-323F]
D5  PMEG6010CEJ,115  [SOD-323F]
D6  value Green  [SML-P1_GREEN]  (hidden comment: SML-P12PTT86)
D7  BZT52C9V1S-7-F  value 9.1V  [sod-323]
D8  value Green  [SML-P1_GREEN]  (hidden comment: SML-P12PTT86)
D9  BZT52C9V1S-7-F  value 9.1V  [sod-323]
D10  value Green  [SML-P1_GREEN]  (hidden comment: SML-P12PTT86)
D11  MMSZ5229BS-7-F  value 4.3V  [sod-323]
D12  PMEG6010CEJ,115  [SOD-323F]
D13  value Green  [SML-P1_GREEN]  (hidden comment: SML-P12PTT86)
D14  BZT52C9V1S-7-F  value 9.1V  [sod-323]
D15  value Red  [SML-P1_RED]  (hidden comment: SML-P12UTT86)
D16  SBR0220T5-7-F  [SOD-523]
D17  SBR0220T5-7-F  [SOD-523]
D18  SBR0220T5-7-F  [SOD-523]
GND_1  5011  [Keystone5011]  (value not drawn)
GND_2  5011  [Keystone5011]  (value not drawn)
J3  PEC03SAAN  [CONN_PEC03SAAN]  (value not drawn)
J4  PEC02SAAN  [CONN_PEC02SAAN]  (value not drawn)
J5  PEC03SAAN  [CONN_PEC03SAAN]  (value not drawn)
J6  1715747  [Phoenix_1715747]
J7  1715747  [Phoenix_1715747]
J8  SSQ-106-02-G-D-RA  [SSQ-106-02-G-D-RA]
J9  1715747  [Phoenix_1715747]
Q4  CSD85301Q2  [DQK0006B]  (parts A,B of 2)
R11  ValueDisplayed: 3.3k  [0603]  (hidden comment: CRCW06033K30JNEA)
R12  ValueDisplayed: 3.3k  [0603]  (hidden comment: CRCW06033K30JNEA)
R13  ValueDisplayed: 680k  [0805_HV]  (hidden comment: CRCW0805680KJNEA)
R14  ValueDisplayed: 680k  [0805_HV]  (hidden comment: CRCW0805680KJNEA)
R15  ValueDisplayed: 59.0k  [0603]  (hidden comment: RC0603FR-0759KL)
R16  ValueDisplayed: 59.0k  [0603]  (hidden comment: RC0603FR-0759KL)
R17  ValueDisplayed: 3.3k  [0603]  (hidden comment: CRCW06033K30JNEA)
R18  ValueDisplayed: 42.2k  [0603]  (hidden comment: RC0603FR-0742K2L)
R19  ValueDisplayed: 42.2k  [0603]  (hidden comment: RC0603FR-0742K2L)
R20  ValueDisplayed: 100k  [0603]  (hidden comment: CRCW0603100KFKEA)
R21  ValueDisplayed: 100k  [0603]  (hidden comment: CRCW0603100KFKEA)
R22  ValueDisplayed: 21.5k  [0805_HV]  (hidden comment: CRCW080521K5FKEA)
R23  ValueDisplayed: 20k  [0805_HV]  (hidden comment: CRCW080520K0JNEA)
R24  ValueDisplayed: 100k  [0805_HV]  (hidden comment: CRCW0805100KFKEA)
R25  ValueDisplayed: 0  [0603]  (hidden comment: CRCW06030000Z0EA)
R26  ValueDisplayed: 0  [0603]  (hidden comment: CRCW06030000Z0EA)
R27  ValueDisplayed: 1.21k  [0603]  (hidden comment: CRCW06031K21FKEA)
R28  ValueDisplayed: 1.21k  [0603]  (hidden comment: CRCW06031K21FKEA)
R29  ValueDisplayed: 2.43k  [0603]  (hidden comment: CRCW06032K43FKEA)
R30  ValueDisplayed: 10.0k  [0603]  (hidden comment: CRCW060310K0FKEA)
R31  ValueDisplayed: 3.3k  [0603]  (hidden comment: CRCW06033K30JNEA)
R32  ValueDisplayed: 59.0k  [0603]  (hidden comment: RC0603FR-0759KL)
R33  ValueDisplayed: 42.2k  [0603]  (hidden comment: RC0603FR-0742K2L)
R34  ValueDisplayed: 470  [0603]  (hidden comment: RC0603FR-07470RL)
R35  ValueDisplayed: 57.6k  [0603]  (hidden comment: RC0603FR-0757K6L)
R36  ValueDisplayed: 10.0k  [0603]  (hidden comment: CRCW060310K0FKEA)
R37  ValueDisplayed: 10.0k  [0603]  (hidden comment: CRCW060310K0FKEA)
R38  ValueDisplayed: 10.0k  [0603]  (hidden comment: CRCW060310K0FKEA)
R39  ValueDisplayed: 2.55k  [0603]  (hidden comment: RC0603FR-072K55L)
R40  ValueDisplayed: 0  [0603]  (hidden comment: CRCW06030000Z0EA)
R41  ValueDisplayed: 1.21k  [0603]  (hidden comment: CRCW06031K21FKEA)
R42  ValueDisplayed: 47.0k  [0603]  (hidden comment: RC0603FR-0747KL)
TP4  5000  [Keystone5000]  (value not drawn)
TP5  5000  [Keystone5000]  (value not drawn)
U6  TLC555CD  [D0008A_N]
U7  TPS92630QPWPRQ1  [PWP0016F_N]
U8  TPS92630QPWPRQ1  [PWP0016F_N]
U9  TPS7A1633QDGNRQ1  [DGN0008C_N]
U10  SN74LVC1G07DBVR  [DBV0005A_N]
U11  TPS92630QPWPRQ1  [PWP0016F_N]
U12  LMV7239QM7  [DCK0005A_N]

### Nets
REVGND: C31.2 C32.1 C33.1 C34.2 C35.1 C36.1 C37.1 C38.2 C39.1 C40.2 C41.1 C42.2 C43.2 C44.1 C45.1 C46.2 C47.2 C48.2 C49.1 C50.1 C51.1 C52.1 C53.1 C54.1 C55.2 C56.1 C57.2 C58.1 C59.2 C60.1 C61.2 C62.1 C63.2 C64.1 C65.1 C66.1 C67.1 C68.1 D6.1(K) D7.2(A) D8.1(K) D9.2(A) D10.1(K) D11.2(A) D13.1(K) D14.2(A) GND_1.1 GND_2.1 J3.3 J6.4 J7.4 J8.1 J8.5 J8.9 J9.4 Q4.1(S1) Q4.4(S2) R18.1 R19.1 R23.1 R24.1 R25.1 R26.1 R27.1 R28.1 R33.1 R36.1 R38.1 R40.1 R41.1 U6.1(GND) U7.10(GND) U7.17(PAD) U8.10(GND) U8.17(PAD) U9.4(GND) U9.9(PAD) U10.3(GND) U11.10(GND) U11.17(PAD) U12.2(V-)  [also labelled GND, TBGND, TURNGND]
/FAULT: C38.1 C40.1 C57.1 J4.1 R21.1 TP4.1 U7.6(FAULT) U8.6(FAULT) U10.2(A) U11.6(FAULT)
/FAULT_S: C42.1 C43.1 C61.1 J4.2 R20.1 TP5.1 U7.7(FAULT_S) U8.7(FAULT_S) U11.7(FAULT_S)
Boost_In: C55.1 R30.2 R35.2 U9.8(IN)
Boost_Out: C39.2 C41.2 C44.2 C45.2 C60.2 C62.2 U7.1(VIN) U8.1(VIN) U8.3(PWM1) U8.4(PWM2) U8.5(PWM3) U11.1(VIN) U11.3(PWM1) U11.4(PWM2) U11.5(PWM3)
EN1: C33.2 C37.2 D9.1(K) D16.2(A) R16.2 R19.2 U8.2(EN)
EN2: C56.2 C58.2 D14.1(K) D17.2(A) R32.2 R33.2 U11.2(EN)
EN3: C32.2 C36.2 D7.1(K) D18.2(A) R15.2 R18.2 U7.2(EN)
LDO_OUT: C35.2 C59.1 C65.2 J3.1 J5.1 R13.2 R20.2 R21.2 R34.2 R37.2 U6.8(VCC) U9.1(OUT) U10.5(VCC) U12.5(V+)
REV1: C68.2 J8.4 J9.1 U11.11(VSNS1) U11.16(IOUT1)
REV2: C66.2 J8.3 J9.2 U11.12(VSNS2) U11.15(IOUT2)
REV3: C64.2 J8.2 J9.3 U11.13(VSNS3) U11.14(IOUT3)
TB1: C54.2 J6.1 J8.12 U8.11(VSNS1) U8.16(IOUT1)
TB2: C52.2 J6.2 J8.11 U8.12(VSNS2) U8.15(IOUT2)
TB3: C50.2 J6.3 J8.10 U8.13(VSNS3) U8.14(IOUT3)
TURN1: C53.2 J7.1 J8.8 U7.11(VSNS1) U7.16(IOUT1)
TURN2: C51.2 J7.2 J8.7 U7.12(VSNS2) U7.15(IOUT2)
TURN3: C49.2 J7.3 J8.6 U7.13(VSNS3) U7.14(IOUT3)
VIN 1: D4.2(A)
VIN 2: D5.2(A)
VIN 3: D3.2(A)
VIN 4: D12.2(A)
NetC31_1: C31.1 D2.1(K) R14.1 U6.2(TRIG) U6.6(THRES)
NetC34_1: C34.1 D5.1(K) R17.2 R22.2
NetC46_1: C46.1 U6.5(CONT)
NetC47_1: C47.1 D11.1(K) Q4.2(G1) R22.1 R23.2
NetC48_1: C48.1 J5.3 R24.2 U6.3(OUT)
NetC63_1: C63.1 R35.1 R36.2 R39.1
NetC67_2: C67.2 Q4.5(G2) R42.1 U12.1(OUT)
NetD2_2: D2.2(A) R13.1 R14.2 U6.7(DISCH)
NetD3_1: D3.1(K) R11.2 R15.1
NetD4_1: D4.1(K) R12.2 R16.1
NetD6_2: D6.2(A) R11.1
NetD8_2: D8.2(A) R12.1
NetD10_2: D10.2(A) R17.1
NetD12_1: D12.1(K) R31.2 R32.1
NetD13_2: D13.2(A) R31.1
NetD15_1: D15.1(K) U10.4(Y)
NetD15_2: D15.2(A) R34.1
NetD16_1: D16.1(K) D17.1(K) D18.1(K) Q4.3(D2) Q4.8(D2)
NetJ3_2: J3.2 U6.4(RESET)
NetJ5_2: J5.2 U7.3(PWM1) U7.4(PWM2) U7.5(PWM3)
NetQ4_6: Q4.6(D1) Q4.7(D1) R29.1
NetR25_2: R25.2 U7.8(TEMP)
NetR26_2: R26.2 U8.8(TEMP)
NetR27_2: R27.2 U7.9(REF)
NetR28_2: R28.2 R29.2 U8.9(REF)
NetR30_1: R30.1 U9.5(EN)
NetR37_1: R37.1 R38.2 U12.4(IN-)
NetR39_2: R39.2 R42.2 U12.3(IN+)
NetR40_2: R40.2 U11.8(TEMP)
NetR41_2: R41.2 U11.9(REF)

Not connected (* = marked no-connect by the designer): U9 2(DNC) 3(PG) 6(NC) 7(DELAY)*; U10 1(NC)

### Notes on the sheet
- TAIL LIGHT/BRAKE LIGHT
- REVERSE LIGHT
- (near J3) OSC ON
- (near J3) OSC OFF
- (near J5) BLINK ON
- (near J5) BLINK OFF
- TURN LIGHT

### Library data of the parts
C31 = GRM219R71E824KA88D: CAP, CERM, 0.82 µF, 25 V, +/- 10%, X7R, 0805; Manufacturer: MuRata; Polarized: N; CompType: Capacitor; Value: 0.82uF; U/M: EA; Cap_F: 0.00000082; Tolerance_%: 10; Value1: Unknown; VDC_V: 25; Value2: 25V; TaMin_C: -55; TaMax_C: 125; Cap_Case: 0805; AEC Category: Q200
C32-C34 C39 C41 C56 C60 = GRM31CR71H475KA12L: CAP, CERM, 4.7 µF, 50 V, +/- 10%, X7R, 1206; Manufacturer: MuRata; Polarized: N; CompType: Capacitor; Value: 4.7uF; U/M: EA; Cap_F: 0.0000047; Tolerance_%: 10; Value1: Unknown; VDC_V: 50; Value2: 50V; TaMin_C: -55; TaMax_C: 125; Cap_Case: 2220; AEC Category: Q200
C35-C38 C40 C42-C45 C47 C58 C61-C63 = 06035C104KAT2A: CAP, CERM, 0.1 µF, 50 V, +/- 10%, X7R, 0603; Manufacturer: AVX; Polarized: N; CompType: Capacitor; Value: 0.1uF; U/M: EA; Cap_F: 0.0000001; Tolerance_%: 10; Value1: Unknown; VDC_V: 50; Value2: 50V; TaMin_C: -55; TaMax_C: 125; AEC Category: Q200
C46 = 0805YC224JAT2A: CAP, CERM, 0.22 µF, 16 V, +/- 5%, X7R, 0805; Manufacturer: AVX; Polarized: N; CompType: Capacitor; Value: 0.22uF; U/M: EA; Cap_F: 0.00000022; Tolerance_%: 5; ESR_ohm: 0.016; Value1: 0.016 ohm; VDC_V: 16; Value2: 16V; TaMin_C: -55; TaMax_C: 125; Cap_Case: 0805; AEC Category: Q200
C48-C54 C64 C66 C68 = 06031C103JAT2A: CAP, CERM, 0.01 µF, 100 V, +/- 5%, X7R, 0603; Manufacturer: AVX; Polarized: N; CompType: Capacitor; Value: 0.01uF; U/M: EA; Cap_F: 0.00000001; Tolerance_%: 5; ESR_ohm: 0.098; Value1: 0.098 ohm; VDC_V: 100; Value2: 100V; TaMin_C: -55; TaMax_C: 125; AEC Category: Q200
C55 = C1608X7R1H104K: CAP, CERM, 0.1 µF, 50 V, +/- 10%, X7R, 0603; Manufacturer: TDK; Polarized: N; CompType: Capacitor; Value: 0.1uF; U/M: EA; Cap_F: 0.0000001; Tolerance_%: 10; ESR_ohm: 0.017; Value1: 0.017 ohm; VDC_V: 50; Value2: 50V; TaMin_C: -55; TaMax_C: 125; AEC Category: Q200
C57 C65 C67 = 0603YC104JAT2A: CAP, CERM, 0.1 µF, 16 V, +/- 5%, X7R, 0603; Manufacturer: AVX; Polarized: N; CompType: Capacitor; Value: 0.1uF; U/M: EA; Cap_F: 0.0000001; Tolerance_%: 5; ESR_ohm: 0.039; Value1: 0.039 ohm; VDC_V: 16; Value2: 16V; TaMin_C: -55; TaMax_C: 125; AEC Category: Q200
C59 = C1608X5R1A226M080AC: CAP, CERM, 22 µF, 10 V, +/- 20%, X5R, 0603; Manufacturer: TDK; Polarized: N; CompType: Capacitor; Value: 22uF; U/M: EA; Cap_F: 0.000022; Tolerance_%: 20; Value1: Unknown; VDC_V: 10; Value2: 10V; TaMin_C: -55; TaMax_C: 85; AEC Category: Q200
D2 = 1N4148W-7-F: Diode, Ultrafast, 100 V, 0.15 A, SOD-123; Manufacturer: Diodes Inc.; U/M: EA; Vf_V: 1.25; Value: 100V; Value1: 0.15A; Value2: 1.25V; Io_A: 0.15; Vr_V: 100; TJmax_C: 150; AEC Category: Q101
D3-D5 D12 = PMEG6010CEJ,115: Diode, Schottky, 60 V, 1 A, SOD-323F; Manufacturer: NXP Semiconductor; U/M: EA; Vf_V: 0.66; Value: 60V; Value1: 1A; Value2: 0.66V; Io_A: 1; Vr_V: 60; TJmax_C: 150; AEC Category: Q101
D6 D8 D10 D13 = SML-P12PTT86: LED, Green, SMD; Manufacturer: Rohm; Type: AlInGaP; Vf_V: 2.2; Value2: 2.2V; Io_A: 0.02; Value1: W; U/M: EA
D7 D9 D14 = BZT52C9V1S-7-F: Diode, Zener, 9.1 V, 200 mW, SOD-323; Manufacturer: Diodes Inc.; SymbolCreator: a0412235; U/M: EA; Power_W: 0.2; Vz_V: 9.1; Value1: 0.2W; RJA_CperW: 625; AEC Category: Q101
D11 = MMSZ5229BS-7-F: Diode, Zener, 4.3 V, 200 mW, SOD-323; Manufacturer: Diodes Inc.; SymbolCreator: a0412235; U/M: EA; Power_W: 0.2; Vz_V: 4.3; Value1: 0.2W; RJA_CperW: 350; AEC Category: Q101
D15 = SML-P12UTT86: LED, Red, SMD; Manufacturer: Rohm; Type: AlInGaP; Vf_V: 2; Value2: 2V; Io_A: 0.02; Value1: W; U/M: EA
D16-D18 = SBR0220T5-7-F: Diode, Schottky, 20 V, 0.2 A, SOD-523; Manufacturer: Diodes Inc.; U/M: EA; Vf_V: 0.47; Value: 20V; Value1: 0.2A; Value2: 0.47V; Io_A: 0.2; Vr_V: 20; AEC Category: Q101
GND_1 GND_2 = 5011: Test Point, Multipurpose, Black, TH; Manufacturer: Keystone; CompType: Test Point Loop; ContactFinish: Silver
J3 J5 = PEC03SAAN: Header, 100mil, 3x1, Tin, TH; Manufacturer: Sullins Connector Solutions; SymbolCreator: a0799628; Pitch_mm: 2.54; Gender: Male; Shrouded: N; Row_Count: 1; Current_A: 3; Voltage_V: 1800; Cert_UL: Y
J4 = PEC02SAAN: Header, 100mil, 2x1, Tin plated, TH; Manufacturer: Sullins Connector Solutions; SymbolCreator: a0412235; U/M: EA
J6 J7 J9 = 1715747: Terminal Block, 5.08mm, 4x1, TH; Manufacturer: Phoenix Contact; SymbolCreator: a0411947
J8 = SSQ-106-02-G-D-RA: Receptacle, 100mil, 6x2, Gold, R/A, TH; Manufacturer: Samtec; SymbolCreator: a0412235
Q4 = CSD85301Q2: MOSFET, N-CH, 20 V, 6.7 A, DQK0006B; Manufacturer: Texas Instruments; Alternate Manufacturer: None; SymbolCreator: a0411947; U/M: EA; ChType: N; Value: 20V; VdsMax_V: 20; Value1: 0.023 ohm; Rdson45_ohm: 0.023; Value2: 4.2 nC; QgTyp_nC: 4.2; Vgs_V: 10; IdsMax_A: 6.7; AEC Category: Q101
R11 R12 R17 R31 = CRCW06033K30JNEA: RES, 3.3 k, 5%, 0.1 W, 0603; Manufacturer: Vishay-Dale; CompType: Resistor; Value: 3.3k; Res_ohm: 3300; Value_Code: 3k30; Tolerance_%: 5; Power_W: 0.1; Value2: 0.1W; VDC_V: 75; TempCo: 200 ppm/C; EIA_Code: E24; U/M: EA; AEC Category: Q200
R13 R14 = CRCW0805680KJNEA: RES, 680 k, 5%, 0.125 W, 0805; Manufacturer: Vishay-Dale; CompType: Resistor; Value: 680k; Res_ohm: 680000; Tolerance_%: 5; Power_W: 0.125; Value2: 0.125W; VDC_V: 150; TempCo: 200 ppm/C; EIA_Code: E24; U/M: EA; AEC Category: Q200
R15 R16 R32 = RC0603FR-0759KL: RES, 59.0 k, 1%, 0.1 W, 0603; Manufacturer: Yageo America; CompType: Resistor; Value: 59.0k; Res_ohm: 59000; Value_Code: 59k0; Tolerance_%: 1; Power_W: 0.1; Value2: 0.1W; VDC_V: 150; TempCo: 200 ppm/C; EIA_Code: E96; U/M: EA; AEC Category: Q200
R18 R19 R33 = RC0603FR-0742K2L: RES, 42.2 k, 1%, 0.1 W, 0603; Manufacturer: Yageo America; CompType: Resistor; Value: 42.2k; Res_ohm: 42200; Value_Code: 42k2; Tolerance_%: 1; Power_W: 0.1; Value2: 0.1W; VDC_V: 150; TempCo: 200 ppm/C; EIA_Code: E96; U/M: EA; AEC Category: Q200
R20 R21 = CRCW0603100KFKEA: RES, 100 k, 1%, 0.1 W, 0603; Manufacturer: Vishay-Dale; CompType: Resistor; Value: 100k; Res_ohm: 100000; Tolerance_%: 1; Power_W: 0.1; Value2: 0.1W; VDC_V: 75; TempCo: 100 ppm/C; EIA_Code: E96; U/M: EA; AEC Category: Q200
R22 = CRCW080521K5FKEA: RES, 21.5 k, 1%, 0.125 W, 0805; Manufacturer: Vishay-Dale; CompType: Resistor; Value: 21.5k; Res_ohm: 21500; Value_Code: 21k5; Tolerance_%: 1; Power_W: 0.125; Value2: 0.125W; VDC_V: 150; TempCo: 100 ppm/C; EIA_Code: E96; U/M: EA; AEC Category: Q200
R23 = CRCW080520K0JNEA: RES, 20 k, 5%, 0.125 W, 0805; Manufacturer: Vishay-Dale; CompType: Resistor; Value: 20k; Res_ohm: 20000; Value_Code: 20k0; Tolerance_%: 5; Power_W: 0.125; Value2: 0.125W; VDC_V: 150; TempCo: 200 ppm/C; EIA_Code: E24; U/M: EA; AEC Category: Q200
R24 = CRCW0805100KFKEA: RES, 100 k, 1%, 0.125 W, 0805; Manufacturer: Vishay-Dale; CompType: Resistor; Value: 100k; Res_ohm: 100000; Tolerance_%: 1; Power_W: 0.125; Value2: 0.125W; VDC_V: 150; TempCo: 100 ppm/C; EIA_Code: E96; U/M: EA; AEC Category: Q200
R25 R26 R40 = CRCW06030000Z0EA: as R2 on sheet TIDA-00678_Boost+Linear LED Driver 1
R27 R28 R41 = CRCW06031K21FKEA: RES, 1.21 k, 1%, 0.1 W, 0603; Manufacturer: Vishay-Dale; CompType: Resistor; Value: 1.21k; Res_ohm: 1210; Value_Code: 1k21; Tolerance_%: 1; Power_W: 0.1; Value2: 0.1W; VDC_V: 75; TempCo: 100 ppm/C; EIA_Code: E96; U/M: EA; AEC Category: Q200
R29 = CRCW06032K43FKEA: RES, 2.43 k, 1%, 0.1 W, 0603; Manufacturer: Vishay-Dale; CompType: Resistor; Value: 2.43k; Res_ohm: 2430; Value_Code: 2k43; Tolerance_%: 1; Power_W: 0.1; Value2: 0.1W; VDC_V: 75; TempCo: 100 ppm/C; EIA_Code: E96; U/M: EA; AEC Category: Q200
R30 R36-R38 = CRCW060310K0FKEA: RES, 10.0 k, 1%, 0.1 W, 0603; Manufacturer: Vishay-Dale; CompType: Resistor; Value: 10.0k; Res_ohm: 10000; Value_Code: 10k0; Tolerance_%: 1; Power_W: 0.1; Value2: 0.1W; VDC_V: 75; TempCo: 100 ppm/C; EIA_Code: E96; U/M: EA; AEC Category: Q200
R34 = RC0603FR-07470RL: RES, 470, 1%, 0.1 W, 0603; Manufacturer: Yageo America; CompType: Resistor; Value: 470; Value_Code: 470R; Tolerance_%: 1; Power_W: 0.1; Value2: 0.1W; VDC_V: 150; TempCo: 200 ppm/C; U/M: EA; AEC Category: Q200
R35 = RC0603FR-0757K6L: RES, 57.6 k, 1%, 0.1 W, 0603; Manufacturer: Yageo America; CompType: Resistor; Value: 57.6k; Res_ohm: 57600; Value_Code: 57k6; Tolerance_%: 1; Power_W: 0.1; Value2: 0.1W; VDC_V: 150; TempCo: 200 ppm/C; EIA_Code: E96; U/M: EA; AEC Category: Q200
R39 = RC0603FR-072K55L: RES, 2.55 k, 1%, 0.1 W, 0603; Manufacturer: Yageo America; CompType: Resistor; Value: 2.55k; Res_ohm: 2550; Value_Code: 2k55; Tolerance_%: 1; Power_W: 0.1; Value2: 0.1W; VDC_V: 150; TempCo: 200 ppm/C; EIA_Code: E96; U/M: EA; AEC Category: Q200
R42 = RC0603FR-0747KL: RES, 47.0 k, 1%, 0.1 W, 0603; Manufacturer: Yageo America; CompType: Resistor; Value: 47.0k; Res_ohm: 47000; Value_Code: 47k0; Tolerance_%: 1; Power_W: 0.1; Value2: 0.1W; VDC_V: 150; TempCo: 200 ppm/C; U/M: EA; AEC Category: Q200
TP4 TP5 = 5000: as TP1 on sheet TIDA-00678_Boost+Linear LED Driver 1
U6 = TLC555CD: LinCMOS Timer, D0008A; Manufacturer: Texas Instruments; SymbolCreator: a0799628; CompType: IC; U/M: EA
U7 U8 U11 = TPS92630QPWPRQ1: Three-Channel Linear LED Driver with Analog and PWM Dimming, PWP0016F; Manufacturer: Texas Instruments; SymbolCreator: a0411947; CompType: IC; U/M: EA
U9 = TPS7A1633QDGNRQ1: 60-V, 5-μA IQ, 100-mA, Low-Dropout VOLTAGE REGULATOR With Enable and Power-Good, DGN0008C; Manufacturer: Texas Instruments; SymbolCreator: a0411947; CompType: IC; U/M: EA
U10 = SN74LVC1G07DBVR: SINGLE BUFFER/DRIVER WITH OPEN-DRAIN OUTPUT, DBV0005A; Alternate PartNumber: SN74LVC1G07DBVT; Manufacturer: Texas Instruments; SymbolCreator: a0411947; CompType: IC; U/M: EA
U12 = LMV7239QM7: Automotive 75 nsec, 2.7V to 5V comparator with Rail-to-Rail Input and Output, DCK0005A; Manufacturer: Texas Instruments; CompType: OpAmp IC

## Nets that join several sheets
REVGND: TIDA-00678_Boost+Linear LED Driver 1 (28 pins), TIDA-00678_Boost+Linear LED Driver 2 (81 pins)
Boost_In: TIDA-00678_Boost+Linear LED Driver 1 (14 pins), TIDA-00678_Boost+Linear LED Driver 2 (C55.1 R30.2 R35.2 U9.8)
Boost_Out: TIDA-00678_Boost+Linear LED Driver 1 (8 pins), TIDA-00678_Boost+Linear LED Driver 2 (15 pins)
VIN 1: TIDA-00678_Boost+Linear LED Driver 1 (J2.2 Q1.1 U1.4), TIDA-00678_Boost+Linear LED Driver 2 (D4.2)
VIN 2: TIDA-00678_Boost+Linear LED Driver 1 (J2.4 Q1.3 U2.4), TIDA-00678_Boost+Linear LED Driver 2 (D5.2)
VIN 3: TIDA-00678_Boost+Linear LED Driver 1 (J2.6 Q2.1 U3.4), TIDA-00678_Boost+Linear LED Driver 2 (D3.2)
VIN 4: TIDA-00678_Boost+Linear LED Driver 1 (J2.8 Q2.3 U4.4), TIDA-00678_Boost+Linear LED Driver 2 (D12.2)

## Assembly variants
001: not fitted FID1 FID2 FID3 R2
